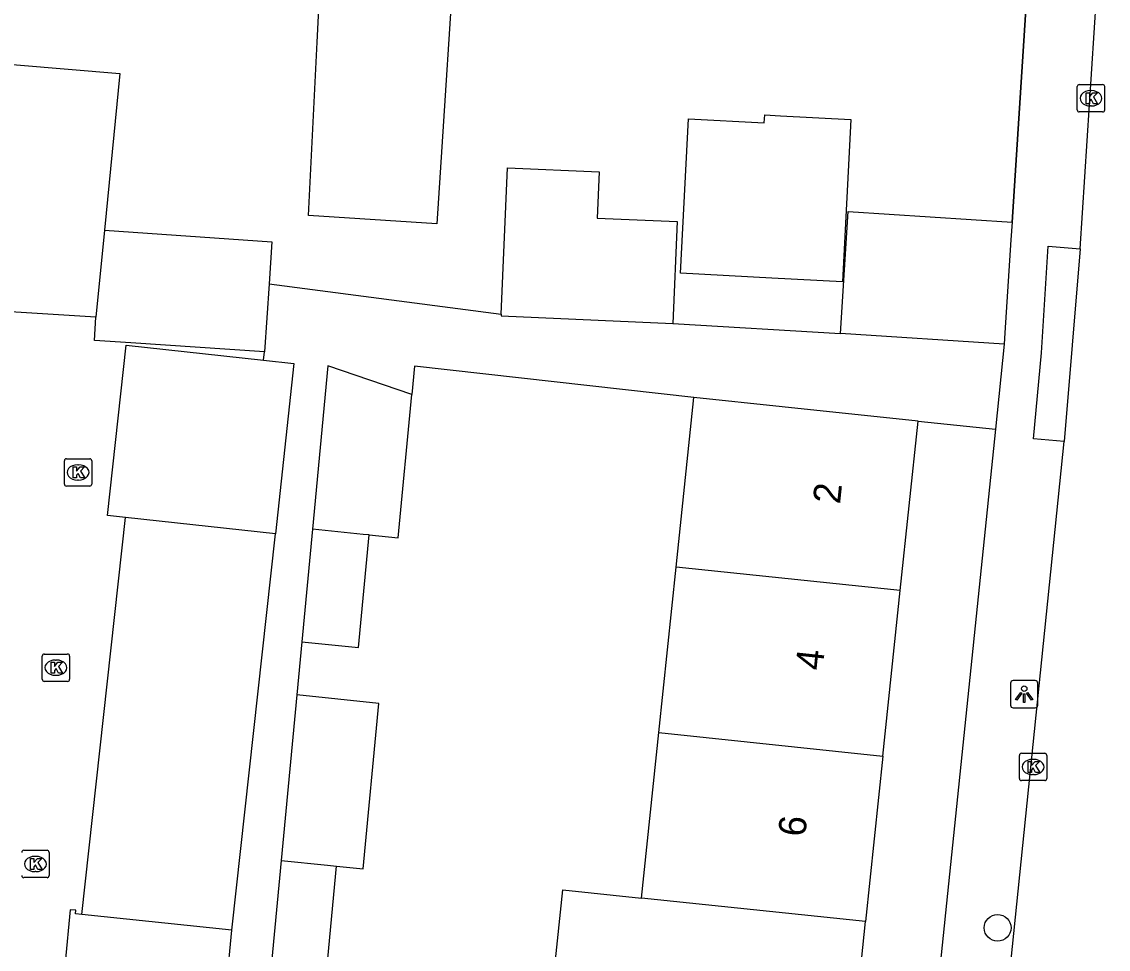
# Model space of a CAD drawing. Extents: x 163010 to 163853, y 382793 to 383982.
# Drawn here: x 163269.15 to 163308.88, y 383393.81 to 383427.74 of the extents above; entities that cross this region are included whole.
import ezdxf

# ---------------------------------------------------------------- set-up
doc = ezdxf.new("R2010")
doc.units = 0
for name, color, linetype in [('IMGEO_Boom', 7, 'Continuous'), ('IMGEO_Kolk', 7, 'Continuous'), ('IMGEO_Lichtpunt', 7, 'Continuous'), ('IMGEO_Muur', 7, 'Continuous'), ('IMGEO_Pand', 7, 'Continuous'), ('IMGEO_Pand_nummerreeks', 7, 'Continuous'), ('IMGEO_Rijbaan_lokaal_open', 7, 'Continuous'), ('IMGEO_Voetpad_open', 7, 'Continuous')]:
    doc.layers.add(name, color=color, linetype=linetype)

msp = doc.modelspace()

# ---------------------------------------------------------------- linework, layer by layer
at = {"layer": 'IMGEO_Boom'}
msp.add_circle((163304.83, 383394.593), 0.489, dxfattribs=at)
at = {"layer": 'IMGEO_Kolk'}
for p, q in [((163307.742, 383424.508), (163307.742, 383425.36)), ((163307.817, 383425.434), (163308.669, 383425.434)), ((163308.23, 383425.214), (163308.255, 383425.214)), ((163308.743, 383425.36), (163308.743, 383424.508)), ((163308.669, 383424.434), (163307.817, 383424.434)), ((163308.253, 383424.654), (163308.228, 383424.654)), ((163270.708, 383410.825), (163270.708, 383411.677)), ((163270.783, 383411.751), (163271.635, 383411.751)), ((163271.709, 383411.677), (163271.709, 383410.825)), ((163271.196, 383411.531), (163271.221, 383411.531)), ((163271.219, 383410.971), (163271.194, 383410.971)), ((163271.635, 383410.751), (163270.783, 383410.751)), ((163269.899, 383403.683), (163269.899, 383404.535)), ((163269.974, 383404.609), (163270.826, 383404.609)), ((163270.9, 383404.535), (163270.9, 383403.683)), ((163270.387, 383404.389), (163270.412, 383404.389)), ((163270.41, 383403.829), (163270.385, 383403.829)), ((163270.826, 383403.609), (163269.974, 383403.609)), ((163305.625, 383400.051), (163305.625, 383400.903)), ((163305.7, 383400.977), (163306.552, 383400.977)), ((163306.626, 383400.903), (163306.626, 383400.051)), ((163306.113, 383400.757), (163306.138, 383400.757)), ((163306.136, 383400.197), (163306.111, 383400.197)), ((163306.552, 383399.977), (163305.7, 383399.977)), ((163269.224, 383397.429), (163270.076, 383397.429)), ((163270.15, 383397.355), (163270.15, 383396.503)), ((163269.637, 383397.209), (163269.662, 383397.209)), ((163269.66, 383396.649), (163269.635, 383396.649)), ((163270.076, 383396.429), (163269.224, 383396.429))]:
    msp.add_line(p, q, dxfattribs=at)
for points in [[(163307.742, 383424.508), (163307.742, 383425.36)], [(163307.817, 383425.434), (163308.669, 383425.434)], [(163308.063, 383425.134), (163308.186, 383425.134), (163308.186, 383424.983), (163308.316, 383425.134), (163308.48, 383425.134), (163308.334, 383424.983), (163308.487, 383424.734), (163308.335, 383424.734), (163308.25, 383424.898), (163308.186, 383424.831), (163308.186, 383424.734), (163308.063, 383424.734), (163308.063, 383425.134)], [(163308.743, 383425.36), (163308.743, 383424.508)], [(163308.669, 383424.434), (163307.817, 383424.434)], [(163270.708, 383410.825), (163270.708, 383411.677)], [(163270.783, 383411.751), (163271.635, 383411.751)], [(163271.709, 383411.677), (163271.709, 383410.825)], [(163271.029, 383411.451), (163271.152, 383411.451), (163271.152, 383411.3), (163271.282, 383411.451), (163271.446, 383411.451), (163271.3, 383411.3), (163271.453, 383411.051), (163271.301, 383411.051), (163271.216, 383411.215), (163271.152, 383411.148), (163271.152, 383411.051), (163271.029, 383411.051), (163271.029, 383411.451)], [(163271.635, 383410.751), (163270.783, 383410.751)], [(163269.899, 383403.683), (163269.899, 383404.535)], [(163269.974, 383404.609), (163270.826, 383404.609)], [(163270.9, 383404.535), (163270.9, 383403.683)], [(163270.22, 383404.309), (163270.343, 383404.309), (163270.343, 383404.158), (163270.473, 383404.309), (163270.637, 383404.309), (163270.491, 383404.158), (163270.644, 383403.909), (163270.492, 383403.909), (163270.407, 383404.073), (163270.343, 383404.006), (163270.343, 383403.909), (163270.22, 383403.909), (163270.22, 383404.309)], [(163270.826, 383403.609), (163269.974, 383403.609)], [(163305.625, 383400.051), (163305.625, 383400.903)], [(163305.7, 383400.977), (163306.552, 383400.977)], [(163306.626, 383400.903), (163306.626, 383400.051)], [(163305.946, 383400.677), (163306.069, 383400.677), (163306.069, 383400.526), (163306.199, 383400.677), (163306.363, 383400.677), (163306.217, 383400.526), (163306.37, 383400.277), (163306.218, 383400.277), (163306.133, 383400.441), (163306.069, 383400.374), (163306.069, 383400.277), (163305.946, 383400.277), (163305.946, 383400.677)], [(163306.552, 383399.977), (163305.7, 383399.977)], [(163269.224, 383397.429), (163270.076, 383397.429)], [(163270.15, 383397.355), (163270.15, 383396.503)], [(163269.47, 383397.129), (163269.593, 383397.129), (163269.593, 383396.978), (163269.723, 383397.129), (163269.887, 383397.129), (163269.741, 383396.978), (163269.894, 383396.729), (163269.742, 383396.729), (163269.657, 383396.893), (163269.593, 383396.826), (163269.593, 383396.729), (163269.47, 383396.729), (163269.47, 383397.129)], [(163270.076, 383396.429), (163269.224, 383396.429)]]:
    msp.add_lwpolyline(points, dxfattribs=at)
for centre, start, end in [((163307.819, 383425.358), 91.552, 178.448), ((163307.819, 383425.358), 91.552, 178.448), ((163308.667, 383425.358), 1.552, 88.448), ((163308.667, 383425.358), 1.552, 88.448), ((163307.819, 383424.51), 181.552, 268.448), ((163307.819, 383424.51), 181.552, 268.448), ((163308.667, 383424.51), 271.552, 358.448), ((163308.667, 383424.51), 271.552, 358.448), ((163270.785, 383411.675), 91.552, 178.448), ((163270.785, 383411.675), 91.552, 178.448), ((163271.633, 383411.675), 1.552, 88.448), ((163271.633, 383411.675), 1.552, 88.448), ((163270.785, 383410.827), 181.552, 268.448), ((163270.785, 383410.827), 181.552, 268.448), ((163271.633, 383410.827), 271.552, 358.448), ((163271.633, 383410.827), 271.552, 358.448), ((163269.976, 383404.533), 91.552, 178.448), ((163269.976, 383404.533), 91.552, 178.448), ((163270.824, 383404.533), 1.552, 88.448), ((163270.824, 383404.533), 1.552, 88.448), ((163269.976, 383403.685), 181.552, 268.448), ((163269.976, 383403.685), 181.552, 268.448), ((163270.824, 383403.685), 271.552, 358.448), ((163270.824, 383403.685), 271.552, 358.448), ((163305.702, 383400.901), 91.552, 178.448), ((163305.702, 383400.901), 91.552, 178.448), ((163306.55, 383400.901), 1.552, 88.448), ((163306.55, 383400.901), 1.552, 88.448), ((163305.702, 383400.053), 181.552, 268.448), ((163305.702, 383400.053), 181.552, 268.448), ((163306.55, 383400.053), 271.552, 358.448), ((163306.55, 383400.053), 271.552, 358.448), ((163269.226, 383397.353), 91.552, 178.448), ((163269.226, 383397.353), 91.552, 178.448), ((163270.074, 383397.353), 1.552, 88.448), ((163270.074, 383397.353), 1.552, 88.448), ((163269.226, 383396.505), 181.552, 268.448), ((163269.226, 383396.505), 181.552, 268.448), ((163270.074, 383396.505), 271.552, 358.448), ((163270.074, 383396.505), 271.552, 358.448)]:
    msp.add_arc(centre, 0.0765, start, end, dxfattribs=at)
for centre, major_axis, ratio, start_param, end_param in [((163308.229, 383424.934), (-0.387, 0.002), 0.722429, 4.712389, 7.853982), ((163308.254, 383424.934), (-0.39, 0.002), 0.717154, 1.570796, 4.712389), ((163271.195, 383411.251), (-0.387, 0.002), 0.722429, 4.712389, 7.853982), ((163271.22, 383411.251), (-0.39, 0.002), 0.717154, 1.570796, 4.712389), ((163270.386, 383404.109), (-0.387, 0.002), 0.722429, 4.712389, 7.853982), ((163270.411, 383404.109), (-0.39, 0.002), 0.717154, 1.570796, 4.712389), ((163306.112, 383400.477), (-0.387, 0.002), 0.722429, 4.712389, 7.853982), ((163306.137, 383400.477), (-0.39, 0.002), 0.717154, 1.570796, 4.712389), ((163269.636, 383396.929), (-0.387, 0.002), 0.722429, 4.712389, 7.853982), ((163269.661, 383396.929), (-0.39, 0.002), 0.717154, 1.570796, 4.712389)]:
    msp.add_ellipse(centre, major_axis=major_axis, ratio=ratio, start_param=start_param, end_param=end_param, dxfattribs=at)
at = {"layer": 'IMGEO_Lichtpunt'}
for p, q in [((163306.204, 383403.637), (163305.396, 383403.637)), ((163306.204, 383403.637), (163305.396, 383403.637)), ((163305.302, 383403.542), (163305.302, 383402.735)), ((163305.302, 383403.542), (163305.302, 383402.735)), ((163306.298, 383402.735), (163306.298, 383403.542)), ((163306.298, 383402.735), (163306.298, 383403.542)), ((163305.396, 383402.641), (163306.204, 383402.641)), ((163305.396, 383402.641), (163306.204, 383402.641))]:
    msp.add_line(p, q, dxfattribs=at)
for points in [[(163305.676, 383403.206), (163305.715, 383403.178), (163305.527, 383402.916), (163305.489, 383402.943), (163305.676, 383403.206)], [(163305.778, 383403.158), (163305.825, 383403.158), (163305.825, 383402.836), (163305.778, 383402.836), (163305.778, 383403.158)], [(163305.888, 383403.178), (163305.926, 383403.205), (163306.113, 383402.943), (163306.074, 383402.915), (163305.888, 383403.178)]]:
    msp.add_lwpolyline(points, dxfattribs=at)
msp.add_circle((163305.801, 383403.34), 0.0994, dxfattribs=at)
for centre, start, end in [((163305.396, 383403.542), 90, 180), ((163305.396, 383403.542), 90, 180), ((163306.204, 383403.542), 0, 90), ((163306.204, 383403.542), 0, 90), ((163305.396, 383402.735), 180, 270), ((163305.396, 383402.735), 180, 270), ((163306.204, 383402.735), 270, 0), ((163306.204, 383402.735), 270, 360)]:
    msp.add_arc(centre, 0.0946, start, end, dxfattribs=at)
at = {"layer": 'IMGEO_Muur'}
msp.add_lwpolyline([(163306.383, 383436.342), (163305.357, 383420.406)], dxfattribs=at)
at = {"layer": 'IMGEO_Pand'}
for points in [[(163287.939, 383437.167), (163284.21, 383437.407), (163283.879, 383432.259), (163285.091, 383432.181), (163284.33, 383420.342), (163279.637, 383420.644), (163279.954, 383426.982), (163280.296, 383433.809)], [(163258.906, 383423.161), (163259.791, 383426.924), (163272.737, 383425.839), (163272.173, 383420.106)], [(163296.298, 383424.035), (163296.314, 383424.329), (163296.891, 383424.299), (163299.467, 383424.164), (163299.156, 383418.226), (163296.58, 383418.361), (163293.234, 383418.536), (163293.53, 383424.18), (163296.298, 383424.035)], [(163286.676, 383417.033), (163286.911, 383422.388), (163290.265, 383422.241), (163290.191, 383420.552), (163293.116, 383420.424), (163292.952, 383416.699)], [(163299.082, 383416.332), (163299.37, 383420.792), (163305.357, 383420.406)], [(163305.357, 383420.406), (163305.315, 383419.756), (163305.096, 383416.362), (163305.069, 383415.946)], [(163272.173, 383420.106), (163271.86, 383416.924)], [(163272.173, 383420.106), (163278.298, 383419.69), (163278.193, 383418.143)], [(163278.193, 383418.143), (163278.024, 383415.659)], [(163271.86, 383416.924), (163268.736, 383417.119)], [(163278.024, 383415.659), (163273.144, 383415.991), (163271.806, 383416.081), (163271.86, 383416.924)], [(163286.676, 383417.033), (163286.673, 383416.975), (163292.952, 383416.699)], [(163305.069, 383415.946), (163299.082, 383416.332)], [(163272.943, 383409.605), (163272.283, 383409.678), (163272.963, 383415.905), (163277.99, 383415.352)], [(163277.99, 383415.352), (163279.104, 383415.229), (163278.425, 383409.002)], [(163283.414, 383414.106), (163280.346, 383415.153), (163279.78, 383409.179)], [(163281.848, 383408.963), (163282.917, 383408.86), (163283.414, 383414.106)], [(163293.078, 383407.788), (163293.726, 383413.985)], [(163301.92, 383413.128), (163296.948, 383413.648), (163293.726, 383413.985)], [(163301.272, 383406.931), (163301.92, 383413.128)], [(163278.425, 383409.002), (163272.943, 383409.605)], [(163279.78, 383409.179), (163279.39, 383405.06)], [(163281.848, 383408.963), (163281.638, 383408.985), (163279.78, 383409.179)], [(163279.39, 383405.06), (163281.458, 383404.844), (163281.848, 383408.963)], [(163292.444, 383401.734), (163293.078, 383407.788)], [(163301.272, 383406.931), (163293.078, 383407.788)], [(163300.638, 383400.877), (163301.272, 383406.931)], [(163279.206, 383403.119), (163278.632, 383397.059)], [(163280.662, 383396.846), (163281.634, 383396.746), (163282.208, 383402.805), (163279.206, 383403.119)], [(163291.811, 383395.68), (163292.444, 383401.734)], [(163292.444, 383401.734), (163300.638, 383400.877)], [(163300.638, 383400.877), (163300.005, 383394.823)], [(163278.632, 383397.059), (163278.058, 383391.001)], [(163278.632, 383397.059), (163280.33, 383396.881), (163280.662, 383396.846)], [(163280.088, 383390.788), (163280.12, 383391.126), (163280.662, 383396.846)], [(163291.178, 383389.627), (163288.303, 383389.928), (163288.936, 383395.981), (163291.811, 383395.68)], [(163300.005, 383394.823), (163291.811, 383395.68)], [(163271.345, 383395.082), (163271.116, 383395.106), (163271.131, 383395.236), (163270.92, 383395.252), (163270.733, 383393.33), (163270.723, 383393.233), (163270.583, 383391.802)], [(163276.832, 383394.51), (163271.345, 383395.082)], [(163276.507, 383391.184), (163276.635, 383392.491), (163276.644, 383392.588), (163276.832, 383394.51)], [(163299.372, 383388.769), (163300.005, 383394.823)]]:
    msp.add_lwpolyline(points, dxfattribs=at)
at = {"layer": 'IMGEO_Rijbaan_lokaal_open'}
for points in [[(163307.85, 383419.423), (163308.875, 383435.24)], [(163307.85, 383419.423), (163307.263, 383412.38)], [(163277.99, 383415.352), (163278.024, 383415.659)], [(163305.156, 383391.761), (163307.263, 383412.38)], [(163271.345, 383395.082), (163272.943, 383409.605)]]:
    msp.add_lwpolyline(points, dxfattribs=at)
at = {"layer": 'IMGEO_Voetpad_open'}
for points in [[(163305.357, 383420.406), (163306.383, 383436.342)], [(163307.263, 383412.38), (163306.141, 383412.475), (163306.432, 383415.624), (163306.676, 383419.522), (163307.85, 383419.423)], [(163278.193, 383418.143), (163286.676, 383417.033)], [(163292.952, 383416.699), (163299.082, 383416.332)], [(163305.069, 383415.946), (163304.748, 383412.836)], [(163293.726, 383413.985), (163283.511, 383415.133), (163283.414, 383414.106)], [(163304.748, 383412.836), (163298.917, 383356.341), (163298.569, 383352.966), (163297.041, 383338.164)], [(163301.92, 383413.128), (163304.748, 383412.836)], [(163276.832, 383394.51), (163278.425, 383409.002)], [(163279.39, 383405.06), (163279.206, 383403.119)]]:
    msp.add_lwpolyline(points, dxfattribs=at)

# ---------------------------------------------------------------- texts
at = {"layer": 'IMGEO_Pand_nummerreeks'}
for s, p in [('2', (163299.066, 383410.071)), ('4', (163298.43, 383403.986)), ('6', (163297.793, 383397.9))]:
    msp.add_text(s, height=1, rotation=84.0281, dxfattribs=at).set_placement(p)

doc.saveas('drawing.dxf')
